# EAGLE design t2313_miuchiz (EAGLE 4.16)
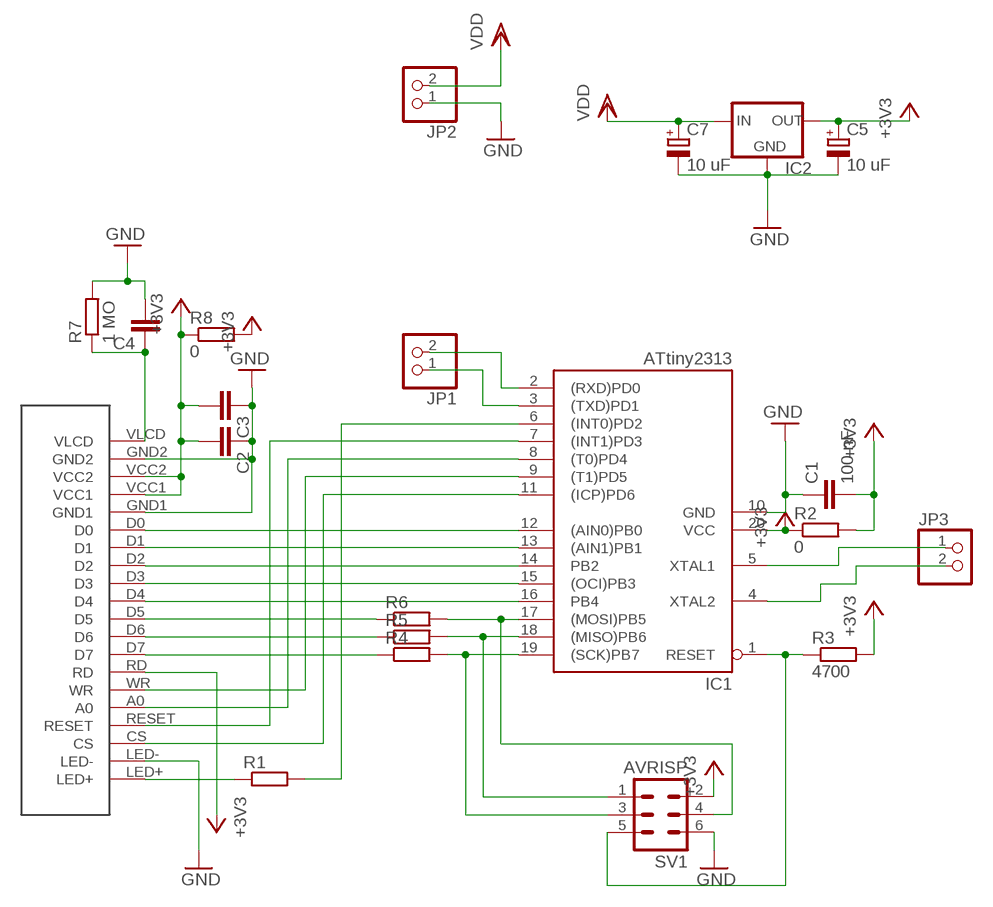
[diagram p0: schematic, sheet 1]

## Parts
C1  100 nF  C-EUC1206  [C1206]
C2  C-EUC0805  [C0805]
C3  C-EUC0805  [C0805]
C4  C-EUC0805  [C0805]
C5  10 uF  CPOL-EU153CLV-0405  [153CLV-0405]
C7  10 uF  CPOL-EU153CLV-0405  [153CLV-0405]
IC1  ATtiny2313  AT90S2313S  [SO20L]
IC2  AD73XXP  [SOT89R]
JP1  PINHD-1X2  [1X02]
JP2  PINHD-1X2  [1X02]
JP3  PINHD-1X2  [1X02]
LCD2  DISPLAY_WOOLWORTH1  [DISPLAYWOOL2]
R1  R-EU_M0805  [M0805]
R2  0  R-EU_M1206  [M1206]
R3  4700  R-EU_M0805  [M0805]
R4  R-EU_M0805  [M0805]
R5  R-EU_M0805  [M0805]
R6  R-EU_M0805  [M0805]
R7  1 MO  R-EU_M0805  [M0805]
R8  0  R-EU_M1206  [M1206]
SV1  AVRISP  MA03-2  [MA03-2]

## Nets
+3V3: C1.2 C2.2 C3.2 C5.+ IC1.20(VCC) IC2.1(OUT) LCD2.RD LCD2.VCC1 LCD2.VCC2 R2.1 R2.2 R3.2 R8.1 R8.2 SV1.2
GND: C1.1 C2.1 C3.1 C4.2 C5.- C7.- IC1.10(GND) IC2.2(GND) JP2.1 LCD2.GND1 LCD2.GND2 LCD2.LED- R7.2 SV1.6
N$1: IC1.12((AIN0)PB0) LCD2.D0
N$2: IC1.13((AIN1)PB1) LCD2.D1
N$3: IC1.14(PB2) LCD2.D2
N$4: IC1.15((OCI)PB3) LCD2.D3
N$5: IC1.16(PB4) LCD2.D4
N$6: IC1.11((ICP)PD6) LCD2.CS
N$7: IC1.18((MISO)PB6) R5.2 SV1.1
N$8: IC1.17((MOSI)PB5) R6.2 SV1.4
N$9: LCD2.LED+ R1.1
N$10: IC1.2((RXD)PD0) JP1.2
N$11: IC1.3((TXD)PD1) JP1.1
N$12: IC1.5(XTAL1) JP3.1
N$13: IC1.9((T1)PD5) LCD2.WR
N$14: LCD2.D5 R6.1
N$15: IC1.1(RESET) R3.1 SV1.5
N$16: IC1.19((SCK)PB7) R4.2 SV1.3
N$17: LCD2.D6 R5.1
N$18: LCD2.D7 R4.1
N$19: IC1.6((INT0)PD2) R1.2
N$20: C4.1 LCD2.VLCD R7.1
N$21: IC1.7((INT1)PD3) LCD2.RESET
N$22: IC1.4(XTAL2) JP3.2
N$23: IC1.8((T0)PD4) LCD2.A0
VDD: C7.+ IC2.3(IN) JP2.2

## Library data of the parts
C1-C4 = rcl:C-EU: CAPACITOR, European symbol
C5 C7 = rcl:CPOL-EU: POLARIZED CAPACITOR, European symbol
IC1 = atmel:AT90S2313: MICROCONTROLLER 2 Kbytes FLASH 128 bytes SRAM 128 bytes EEPROM UART
IC2 = ad73xx:AD73XX: Positiv Voltage Regulators www.torex.co.jp/english/product/pro02/pdf/0201_xc62fp.pdf
JP1-JP3 = pinhead:PINHD-1X2: PIN HEADER
LCD2 = Display_woolworthv2:DISPLAY_WOOLWORTH1
R1-R8 = rcl:R-EU_: RESISTOR, European symbol
SV1 = con-lstb:MA03-2: PIN HEADER

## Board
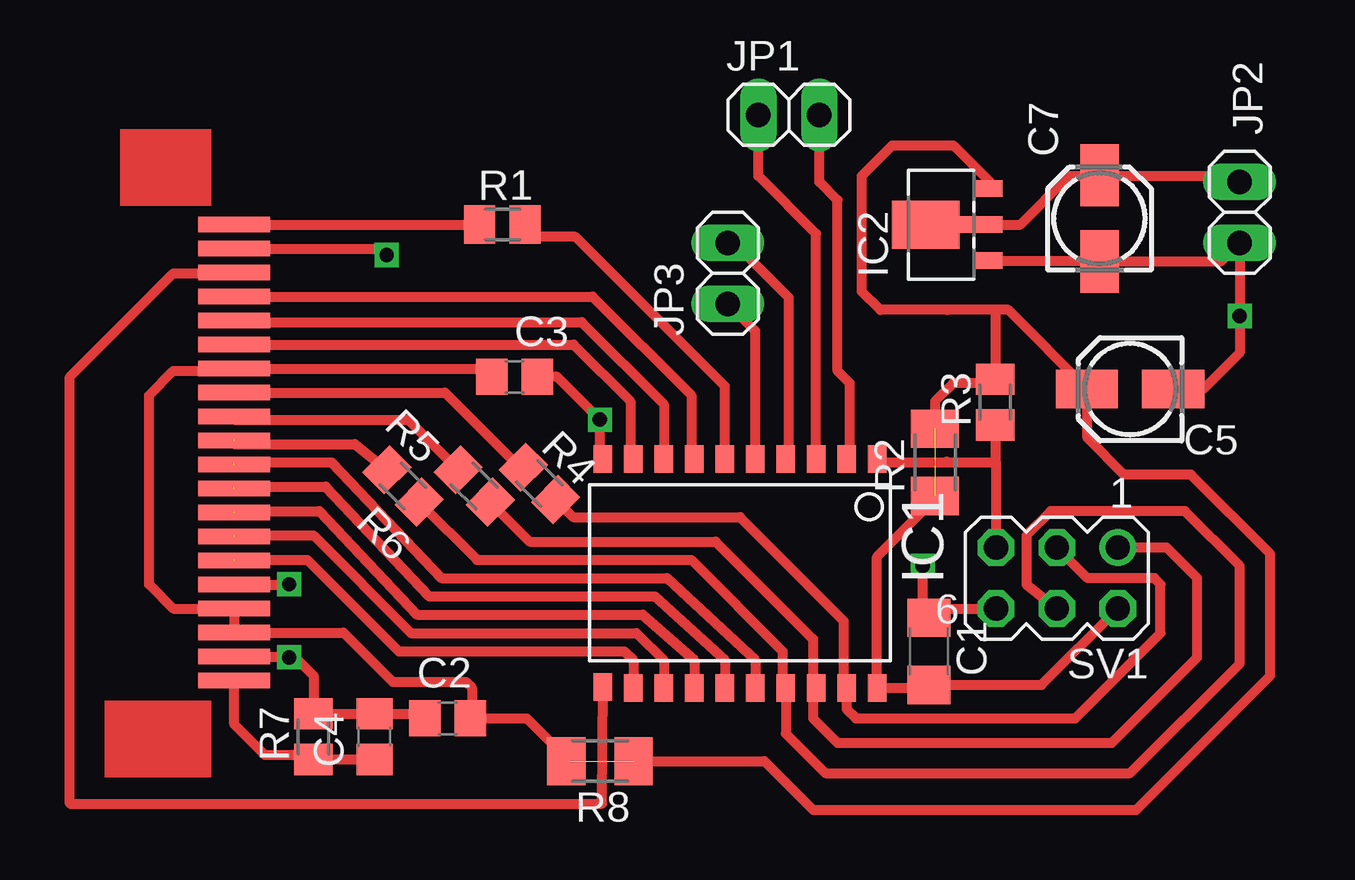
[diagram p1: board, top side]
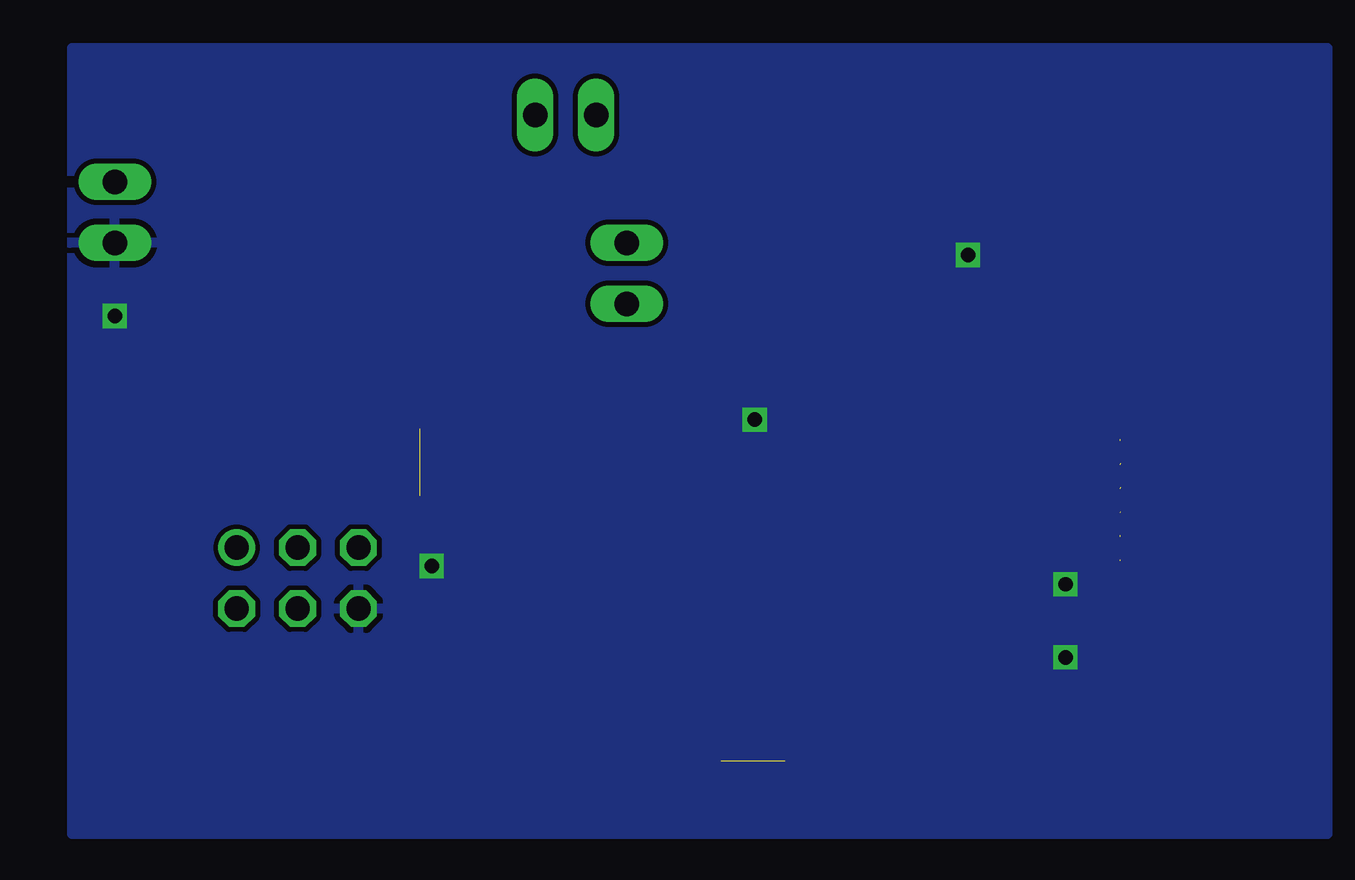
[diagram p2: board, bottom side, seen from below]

No outline drawn. Coordinates in mm, seen from the top.
Copper layers (1*16): Top 0.035mm / dielectric 1.5mm / Bottom 0.035mm
Design rules "default": minimum track width 10mil, minimum drill 24mil, track to track 8mil, track to pad 8mil, pad to pad 8mil, via to via 8mil, smd to smd 8mil, copper to edge 40mil, drill to drill 8mil, minimum pad ring 10mil, minimum via ring 8mil, stop-mask expansion 4mil, vias tented up to drill 0mil, thermal gap 10mil

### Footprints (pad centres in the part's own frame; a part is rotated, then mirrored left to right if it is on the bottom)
C1206 = smd 1.6 x 1.8: 1 -1.4,0; 2 1.4,0
C0805 = smd 1.3 x 1.5: 1 -0.95,0; 2 0.95,0
153CLV-0405 = smd 2.6 x 1.6: + 1.8,0; - -1.8,0
SO20L = smd 0.762 x 1.143: 1 -5.08,-5.131; 2 -3.81,-5.131; 3 -2.54,-5.131; 4 -1.27,-5.131; 5 0,-5.131; 6 1.27,-5.131; 7 2.54,-5.131; 8 3.81,-5.131; 9 5.08,-5.131; 10 6.35,-5.131; 11 6.35,4.369; 12 5.08,4.394; 13 3.81,4.394; 14 2.54,4.394; 15 1.27,4.394; 16 0,4.394; 17 -1.27,4.394; 18 -2.54,4.394; 19 -3.81,4.394; 20 -5.08,4.394
SOT89R = smd 0.7 x 1.1: 1 1.5,-1.75; 2 -1.5,-1.75 | smd 0.7 x 1.8: 3 0,-1.4 | smd 2 x 2.8: 4 0,0.9
1X02 = drill 1.016 long: 1 -1.27,0; 2 1.27,0
DISPLAYWOOL2 = smd 3 x 0.635: A0 0,-4; CS 0,-2; D0 0,-14; D1 0,-13; D2 0,-12; D3 0,-11; D4 0,-10; D5 0,-9; D6 0,-8; D7 0,-7; GND1 0,-15; GND2 0,-18; LED+ 0,0; LED- 0,-1; RD 0,-6; RESET 0,-3; VCC1 0,-16; VCC2 0,-17; VLCD 0,-19; WR 0,-5
M0805 = smd 1.3 x 1.6: 1 -0.95,0; 2 0.95,0
M1206 = smd 1.6 x 2: 1 -1.4,0; 2 1.4,0
MA03-2 = drill 1.016 round: 1 -2.54,-1.27 | drill 1.016 octagon: 2 -2.54,1.27; 3 0,-1.27; 4 0,1.27; 5 2.54,-1.27; 6 2.54,1.27

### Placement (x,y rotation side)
C1  75.18,24.89 270 top
C2  55.12,22.1 0 top
C3  57.91,36.32 180 top
C4  52.07,21.34 90 top
C5  83.57,35.81 180 top
C7  82.3,42.93 90 top
IC1  67.94,27.77 180 top
IC2  75.95,42.67 90 top
JP1  69.34,47.24 0 top
JP2  88.14,43.18 90 top
JP3  66.8,40.64 90 top
LCD2  46.23,42.67 0 top
R1  57.4,42.67 0 top
R2  75.44,32.77 90 top
R3  77.95,35.27 90 top
R4  58.94,31.89 315 top
R5  56.23,31.78 315 top
R6  53.26,31.78 315 top
R7  49.53,21.34 90 top
R8  61.47,20.32 180 top
SV1  80.52,27.94 180 top

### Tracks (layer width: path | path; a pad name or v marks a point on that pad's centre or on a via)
+3V3  (2 unrouted)
  Top 0.406: IC2.1 77.7,44.48 76.2,45.97 73.66,45.97 72.39,44.7 72.39,39.88 73.15,39.12 75.95,39.12 77.98,39.12 | 77.98,39.12 78.49,39.12 81.79,35.81 | LCD2.VCC2 46.23,25.65 | LCD2.VCC2 LCD2.VCC1 43.69,26.67 42.67,27.69 42.67,35.56 43.69,36.58 46.23,36.58 LCD2.RD 56.55,36.67 56.9,36.32 C3.2 | SV1.2 79.88,23.49 C1.2 75.18,23.37 IC1.20 73.02,28.83 75.44,31.24 R2.1 | 77.98,39.12 77.95,39.08 R3.2 77.95,36.1 77.98,36.07 76.2,36.07 75.44,35.31 R2.2 | LCD2.VCC2 50.78,25.67 52.83,23.62 55.88,23.62 56.13,23.37 56.13,22.1 | 56.13,22.1 C2.2 | R8.2 60.2,20.32 58.42,22.1 56.13,22.1 | R8.1 68.33,20.32 70.36,18.29 83.82,18.29 89.41,23.88 89.41,28.96 86.11,32.26 83.31,32.26 81.79,33.78 81.79,35.81 | 81.79,35.81 C5.+
GND  (via drill 0.6)
  Top 0.406: 82.3,41.15 87.38,41.15 JP2.1 v88.14,38.86 88.14,37.34 86.61,35.81 C5.- | 82.3,41.15 C7.- | IC2.2 82.27,41.17 82.3,41.15 | C1.1 75.18,26.16 | SV1.6 75.69,26.67 75.18,26.16 | IC1.10 61.59,33.02 61.47,33.02 v61.47,34.54 59.69,36.32 C3.1 | v74.93,28.45 74.93,26.42 75.18,26.16 | LCD2.LED- 52.31,41.67 v52.58,41.4 | LCD2.GND1 48.5,27.67 v48.51,27.69 | LCD2.GND2 48.48,24.67 v48.51,24.64 48.77,24.64 49.53,23.88 R7.2 52,22.29 arc90 52.07,22.35 C4.2 53.91,22.29 54.1,22.1 C2.1
  pour Bottom: 37.59,50.04 37.59,17.27 89.92,17.27 89.92,50.04
N$1  (1 unrouted)
  Top 0.406: IC1.12 62.86,24.51 62.48,24.89 53.09,24.89 49.28,28.7 46.23,28.7
N$2  (1 unrouted)
  Top 0.406: IC1.13 64.13,24.51 62.99,25.65 53.59,25.65 49.53,29.72 46.23,29.72 46.21,29.7
N$3  (1 unrouted)
  Top 0.406: IC1.14 65.4,24.51 63.25,26.42 53.85,26.42 49.78,30.73 46.23,30.73 46.2,30.7
N$4  (1 unrouted)
  Top 0.406: IC1.15 66.67,24.51 63.75,27.18 54.36,27.18 50.04,31.75 46.23,31.75 46.2,31.72
N$5  (1 unrouted)
  Top 0.406: IC1.16 67.94,24.51 64.26,27.94 54.86,27.94 50.29,32.77 46.23,32.77 46.2,32.73
N$6
  Top 0.406: IC1.11 61.56,18.54 39.37,18.54 39.37,36.32 43.69,40.64 46.23,40.64 LCD2.CS
N$7
  Top 0.406: 70.36,23.37 70.36,22.1 71.37,21.08 82.8,21.08 86.36,24.64 86.36,27.94 85.09,29.21 SV1.1 | R5.2 58.54,29.46 66.29,29.46 70.36,25.4 70.36,23.37 | 70.36,23.37 IC1.18
N$8
  Top 0.406: R6.2 56.34,28.7 65.28,28.7 69.09,24.89 69.09,23.37 IC1.17 69.21,21.46 70.87,19.81 83.57,19.81 88.14,24.38 88.14,28.45 85.85,30.73 80.26,30.73 79.25,29.72 79.25,27.69 SV1.4
N$9
  Top 0.406: LCD2.LED+ R1.1
N$10
  Top 0.406: JP1.2 70.61,44.45 71.37,43.69 71.37,36.58 71.88,36.07 71.88,33.02 IC1.2 | IC1.2 71.63,32.77 | IC1.2
N$11
  Top 0.406: IC1.3 70.48,42.29 68.07,44.7 68.07,46.99 68.33,47.24 JP1.1
N$12
  Top 0.406: IC1.5 67.94,38.23 JP3.1
N$13
  Top 0.406: LCD2.WR 60.37,37.67 62.74,35.31 62.74,33.27 62.99,33.02 IC1.9
N$14  (1 unrouted)
  Top 0.406: 46.23,33.74 46.23,33.53 51.26,33.53 R6.1
N$15
  Top 0.406: IC1.1 73.15,32.77 75.95,32.77 | 75.95,32.77 75.91,32.8 | R3.1 77.98,34.29 77.98,32.77 | 77.98,32.77 SV1.5 | 75.95,32.77 77.98,32.77
N$16
  Top 0.406: R4.2 60.35,30.48 67.31,30.48 71.63,26.16 71.63,23.37 IC1.19 71.75,22.48 72.14,22.1 81.28,22.1 84.84,25.65 84.84,27.69 84.58,27.94 81.79,27.94 SV1.3
N$17
  Top 0.406: LCD2.D6 46.23,34.54 53.46,34.54 R5.1
N$18
  Top 0.406: R4.1 58.21,32.56 58.17,32.51 55.01,35.67 LCD2.D7
N$19
  Top 0.406: IC1.6 66.67,35.94 60.45,42.16 58.67,42.16 58.17,42.67 R1.2
N$20
  Top 0.406: C4.1 52.07,20.32 arc90 52,20.39 R7.1 49.53,20.57 47.5,20.57 46.23,21.84 LCD2.VLCD
N$21
  Top 0.406: LCD2.RESET 61.17,39.67 65.28,35.56 65.28,33.02 IC1.7
N$22
  Top 0.406: JP3.2 67.06,41.91 69.34,39.62 69.34,33.02 IC1.4
N$23
  Top 0.406: IC1.8 64.13,35.18 60.71,38.61 46.48,38.61 46.42,38.67 LCD2.A0
VDD
  Top 0.406: JP2.2 88.14,44.7 82.55,44.7 C7.+ 82.06,44.73 82.04,44.7 81.03,44.7 78.99,42.67 IC2.3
